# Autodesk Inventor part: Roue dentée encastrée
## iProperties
Created: 2002-05
Part Number: Roue dentée encastrée
Material: Par défaut
Document SubType Name: Modélisation
Designer: Flavien MARTY
Control State: 0
Master: False
Checked Out: False
Shininess: 20.0
Length Units: 11269
Angle Units: 11279
Time Units: 11290
Mass Units: 11283
Length Display Precision: 3
Angle Display Precision: 2
Compacted: True
Density: 0.0
Volumn: 0.0
Area: 0.0
PropertySet Name: Model Information
Author: Flavien MARTY
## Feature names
1. Extrusion1
2. Extrusion2
3. Perçage1 [Hole]
